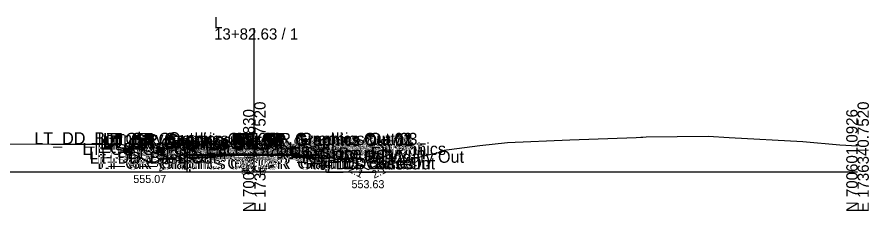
# Model space of a CAD drawing. Extents: x -26 to 697, y -10 to 2642.
# Drawn here: x 91 to 302.8, y 2190.3 to 2238.5 of the extents above; entities that cross this region are included whole.
import ezdxf

# ---------------------------------------------------------------- set-up
doc = ezdxf.new("R2010")
doc.units = 0
for name, color, linetype in [('Default', 7, 'Continuous'), ('Exist CMT Pavement', 7, 'Continuous'), ('Exist Cross Section Cell', 7, 'Continuous'), ('Exist XS Center Line Elevation Label', 7, 'Continuous'), ('Exist XS Ground Line', 7, 'Continuous'), ('Prop CMT Ditch DDE', 7, 'Continuous'), ('Prop CMT Guardrail Graphics', 7, 'Continuous'), ('Prop CMT Pvmt Course 1', 7, 'Continuous'), ('Prop CMT Pvmt Course 1 Wedge', 7, 'Continuous'), ('Prop CMT Pvmt Course 2', 7, 'Continuous'), ('Prop CMT Pvmt Course 2 Wedge', 7, 'Continuous'), ('Prop CMT Pvmt Surface', 7, 'Continuous'), ('Prop CMT Pvmt Surface Shoulder', 7, 'Continuous'), ('Prop CMT Pvmt Wedge Surface 1', 7, 'Continuous'), ('Prop CMT Pvmt Wedge Surface 2', 7, 'Continuous'), ('Prop CMT Shld Paved Course 1', 7, 'Continuous'), ('Prop CMT Shld Paved Course 2', 7, 'Continuous'), ('Prop CMT Slope Grass', 7, 'Continuous'), ('Prop CMT Subgrade Earthwork', 7, 'Continuous'), ('Prop XS Ditch Slope Text', 7, 'Continuous'), ('Prop XS Ditch Standard Text', 7, 'Continuous'), ('Prop XS SE Text', 7, 'Continuous'), ('Prop XS Side Slope Text', 7, 'Continuous')]:
    doc.layers.add(name, color=color, linetype=linetype)

msp = doc.modelspace()

# ---------------------------------------------------------------- linework, layer by layer
at = {"layer": 'Exist CMT Pavement'}
for points in [[(150, 2204.17), (140.37, 2204.02)], [(140.37, 2204.02), (145.19, 2204.1)], [(145.19, 2204.1), (150, 2204.17)], [(154.79, 2204.13), (150, 2204.17)], [(150, 2204.17), (159.58, 2204.09)], [(159.58, 2204.09), (154.79, 2204.13)]]:
    msp.add_lwpolyline(points, dxfattribs=at)
at = {"layer": 'Exist Cross Section Cell'}
for p, q in [((150, 2200), (150, 2235.67)), ((0, 2200), (150, 2200)), ((150, 2200), (300, 2200))]:
    msp.add_line(p, q, dxfattribs=at)
at = {"layer": 'Exist XS Ground Line'}
msp.add_lwpolyline([(89.24, 2206.94), (99.57, 2206.93), (116.83, 2206.87), (124.48, 2204.88), (132.24, 2202.4), (133.49, 2202.76), (135.76, 2203.41), (138.72, 2203.78), (140.37, 2204.02), (148.63, 2204.17), (149.79, 2204.17), (151.03, 2204.16), (159.58, 2204.09), (160.58, 2203.96), (162.84, 2203.7), (166.59, 2202.7), (167.19, 2202.54), (170.32, 2203.17), (171.54, 2203.41), (175.17, 2203.26), (177.21, 2203.12), (179.71, 2202.62), (183.64, 2201.9), (194.2, 2204.49), (195.81, 2204.79), (196.58, 2205.35), (206.07, 2206.6), (212.96, 2207.35), (228.45, 2207.95), (244.94, 2208.55), (246.11, 2208.61), (246.64, 2208.62), (247.45, 2208.68), (262.88, 2208.87), (268.12, 2208.57), (286.38, 2207.55), (295.59, 2206.69), (300, 2206.51)], dxfattribs=at)
at = {"layer": 'Prop CMT Ditch DDE'}
for points in [[(124.59, 2202.07), (114.97, 2206.87)], [(129.73, 2203.2), (126.73, 2203.14), (124.59, 2202.07)], [(170.36, 2203.17), (173.36, 2203.11), (178.34, 2200.63)], [(124.59, 2202.07), (124.59, 2202.07)], [(178.34, 2200.63), (181.62, 2202.27)], [(178.34, 2200.63), (178.34, 2200.63)]]:
    msp.add_lwpolyline(points, dxfattribs=at)
at = {"layer": 'Prop CMT Guardrail Graphics'}
for points in [[(132.68, 2200.71), (132.68, 2206.71)], [(132.68, 2206.71), (134.01, 2206.71), (134.28, 2206.42)], [(134.28, 2205.84), (134.01, 2205.55), (133.34, 2205.55)], [(133.34, 2205.55), (133.34, 2200.71)], [(134.28, 2206.42), (134.01, 2206.13)], [(134.01, 2206.13), (134.28, 2205.84)], [(167.36, 2206.71), (166.03, 2206.71), (165.76, 2206.42)], [(165.76, 2206.42), (166.03, 2206.13)], [(166.03, 2206.13), (165.76, 2205.84)], [(165.76, 2205.84), (166.03, 2205.55), (166.7, 2205.55)], [(166.7, 2205.55), (166.7, 2200.71)], [(167.36, 2200.71), (167.36, 2206.71)], [(133.34, 2200.71), (132.68, 2200.71)], [(166.7, 2200.71), (167.36, 2200.71)]]:
    msp.add_lwpolyline(points, dxfattribs=at)
at = {"layer": 'Prop CMT Pvmt Course 1'}
for points in [[(150, 2204.53), (139, 2204.31)], [(139, 2204.31), (139, 2204.1)], [(139, 2204.1), (140.37, 2204.13)], [(140.37, 2204.23), (150, 2204.42)], [(140.37, 2204.13), (140.37, 2204.23)], [(150, 2204.32), (150, 2204.53)], [(150, 2204.53), (161, 2204.31)], [(150, 2204.32), (150, 2204.53)], [(150, 2204.42), (150, 2204.32), (150, 2204.32)], [(159.58, 2204.23), (150, 2204.42)], [(150, 2204.42), (150, 2204.32), (150, 2204.32)], [(159.58, 2204.13), (159.58, 2204.23)], [(161, 2204.1), (159.58, 2204.13)], [(161, 2204.31), (161, 2204.1)]]:
    msp.add_lwpolyline(points, dxfattribs=at)
at = {"layer": 'Prop CMT Pvmt Course 1 Wedge'}
for points in [[(150, 2204.42), (140.37, 2204.23)], [(150, 2204.42), (159.58, 2204.23)]]:
    msp.add_lwpolyline(points, dxfattribs=at)
at = {"layer": 'Prop CMT Pvmt Course 2'}
for points in [[(140.37, 2204.13), (139, 2204.1)], [(139, 2204.1), (139, 2203.64)], [(139, 2203.64), (140.37, 2203.67)], [(140.37, 2203.67), (140.37, 2204.13)], [(159.58, 2203.67), (159.58, 2204.13)], [(159.58, 2204.13), (161, 2204.1)], [(161, 2203.64), (159.58, 2203.67)], [(161, 2204.1), (161, 2203.64)]]:
    msp.add_lwpolyline(points, dxfattribs=at)
at = {"layer": 'Prop CMT Pvmt Course 2 Wedge'}
for points in [[(150, 2204.32), (140.37, 2204.13)], [(150, 2204.32), (159.58, 2204.13)]]:
    msp.add_lwpolyline(points, dxfattribs=at)
at = {"layer": 'Prop CMT Pvmt Surface'}
for points in [[(150, 2204.53), (139, 2204.31)], [(150, 2204.53), (161, 2204.31)]]:
    msp.add_lwpolyline(points, dxfattribs=at)
at = {"layer": 'Prop CMT Pvmt Surface Shoulder'}
for points in [[(139, 2204.31), (134.29, 2204.21)], [(161, 2204.31), (165.75, 2204.21)]]:
    msp.add_lwpolyline(points, dxfattribs=at)
at = {"layer": 'Prop CMT Pvmt Wedge Surface 1'}
for points in [[(139, 2204.1), (139, 2204.31)], [(140.37, 2204.13), (139, 2204.1)], [(150, 2204.42), (140.37, 2204.23)], [(140.37, 2204.23), (140.37, 2204.13)], [(150, 2204.53), (150, 2204.32), (150, 2204.32), (150, 2204.42)], [(150, 2204.53), (150, 2204.32), (150, 2204.32), (150, 2204.42)], [(150, 2204.42), (159.58, 2204.23)], [(159.58, 2204.23), (159.58, 2204.13)], [(159.58, 2204.13), (161, 2204.1)], [(161, 2204.1), (161, 2204.31)]]:
    msp.add_lwpolyline(points, dxfattribs=at)
at = {"layer": 'Prop CMT Pvmt Wedge Surface 2'}
for points in [[(150, 2204.32), (139, 2204.1)], [(139, 2204.1), (139, 2204.31)], [(150, 2204.53), (150, 2204.32)], [(150, 2204.53), (150, 2204.32)], [(150, 2204.32), (161, 2204.1)], [(161, 2204.1), (161, 2204.31)]]:
    msp.add_lwpolyline(points, dxfattribs=at)
at = {"layer": 'Prop CMT Shld Paved Course 1'}
for points in [[(139, 2204.31), (134.29, 2204.21), (134.08, 2204)], [(134.08, 2204), (139, 2204.1)], [(139, 2204.1), (139, 2204.31)], [(161, 2204.31), (165.75, 2204.21), (165.96, 2204)], [(161, 2204.1), (161, 2204.31)], [(165.96, 2204), (161, 2204.1)]]:
    msp.add_lwpolyline(points, dxfattribs=at)
at = {"layer": 'Prop CMT Shld Paved Course 2'}
for points in [[(139, 2204.1), (134.08, 2204), (134.07, 2204), (133.6, 2203.53)], [(133.6, 2203.53), (139, 2203.64)], [(139, 2203.64), (139, 2204.1)], [(161, 2204.1), (165.96, 2204), (165.97, 2204), (166.44, 2203.53)], [(161, 2203.64), (161, 2204.1)], [(166.44, 2203.53), (161, 2203.64)]]:
    msp.add_lwpolyline(points, dxfattribs=at)
at = {"layer": 'Prop CMT Slope Grass'}
for points in [[(131.28, 2203.97), (129.73, 2203.2)], [(134.28, 2204.21), (131.28, 2203.97)], [(134.29, 2204.21), (134.28, 2204.21)], [(165.75, 2204.21), (165.76, 2204.21)], [(165.76, 2204.21), (168.76, 2203.97)], [(168.76, 2203.97), (170.36, 2203.17)]]:
    msp.add_lwpolyline(points, dxfattribs=at)
at = {"layer": 'Prop CMT Subgrade Earthwork'}
for points in [[(133.6, 2203.53), (133.02, 2204.11)], [(139, 2203.64), (133.6, 2203.53)], [(140.37, 2203.67), (139, 2203.64)], [(140.37, 2203.67), (140.39, 2204.02)], [(159.58, 2203.67), (159.56, 2204.09)], [(159.58, 2203.67), (161, 2203.64)], [(161, 2203.64), (166.44, 2203.53)], [(166.44, 2203.53), (167.02, 2204.11)]]:
    msp.add_lwpolyline(points, dxfattribs=at)

# ---------------------------------------------------------------- texts
at = {"layer": 'Default'}
for s, p in [('LT_DD_Boundary Out', (95.31, 2206.87)), ('LT_GR_Graphics Out 03', (111.03, 2206.71)), ('LT_GR_Graphics Out 02', (112.41, 2206.71)), ('LT_GR_Graphics Out 01', (113.12, 2206.42)), ('RT_GR_Graphics Out 02', (144.26, 2206.71)), ('RT_GR_Graphics Out 01', (144.42, 2206.42)), ('RT_GR_Graphics Out 03', (145.54, 2206.71)), ('LT_GS_OS_GR_Face_Graphics', (107.27, 2204.21)), ('LT_GR_Graphics Out 06', (111.66, 2205.55)), ('LT_GR_Graphics Out 07', (112.28, 2205.55)), ('LT_GR_Graphics Out 09', (112.33, 2206.13)), ('LT_GR_Graphics Out 08', (112.59, 2205.84)), ('LT_PV1_OEOT', (126.6, 2204.31)), ('RT_PV2_IEEOP', (137.14, 2204.32)), ('LT_PV2_IEEOP', (137.32, 2204.32)), ('RT_PV1_IEEOP', (137.5, 2204.42)), ('LT_PV1_IEEOP', (137.68, 2204.42)), ('RT_GS_OS_GR_Face_Graphics', (138.57, 2204.21)), ('PV2_PGL', (142.05, 2204.32)), ('PV1_PGL', (142.41, 2204.53)), ('RT_GR_Graphics Out 08', (143.9, 2205.84)), ('RT_GR_Graphics Out 07', (144.13, 2205.55)), ('RT_GR_Graphics Out 09', (144.18, 2206.13)), ('RT_GR_Graphics Out 06', (144.84, 2205.55)), ('RT_PV1_OEOT', (148.42, 2204.31)), ('LT_DD_Boundary In', (108.91, 2203.14)), ('LT_Sub_Trench_Out_DLT', (110.97, 2204.11)), ('LT_Sub_Trench_Out', (115.93, 2203.53)), ('LT_GS_OS_CTL', (117.67, 2203.97)), ('LT_PS2_Shelf_Out', (118.04, 2204)), ('LT_Slope_Fill', (118.44, 2203.2)), ('LT_PS2_OEOP', (121.44, 2204)), ('LT_PS1_OEOP', (122.01, 2204.21)), ('LT_PV_Sub_Tie_Out', (122.88, 2204.02)), ('LT_PV_OEEOP_EG', (124.16, 2204.02)), ('LT_PV2_OEOT', (126.24, 2204.1)), ('LT_Sub_OEOT', (126.31, 2203.64)), ('LT_PV2_OEEOP', (126.55, 2204.13)), ('LT_Sub_OEEOP', (126.62, 2203.67)), ('LT_PV1_OEEOP', (126.91, 2204.23)), ('LT_PV_EG_TestPt', (130.31, 2204.1)), ('RT_PV_IEEOP_EG', (134.76, 2204.17)), ('LT_PV_IEEOP_EG', (134.93, 2204.17)), ('RT_PV_EG_TestPt', (139.73, 2204.13)), ('RT_PV_Sub_Tie_Out', (141.88, 2204.09)), ('RT_PV_OEEOP_EG', (143.19, 2204.09)), ('RT_Sub_Trench_Out_DLT', (144.79, 2204.11)), ('RT_PV2_OEEOP', (145.58, 2204.13)), ('RT_Sub_OEEOP', (145.65, 2203.67)), ('RT_PV1_OEEOP', (145.94, 2204.23)), ('RT_PV2_OEOT', (148.06, 2204.1)), ('RT_Sub_OEOT', (148.13, 2203.64)), ('RT_Sub_Trench_Out', (148.59, 2203.53)), ('RT_PS2_Shelf_Out', (149.77, 2204)), ('RT_PS2_OEOP', (153.14, 2204)), ('RT_PS1_OEOP', (153.29, 2204.21)), ('RT_GS_OS_CTL', (154.97, 2203.97)), ('RT_DD_Boundary In', (155.36, 2203.11)), ('RT_Slope_Fill', (158.9, 2203.17)), ('RT_DD_Boundary Out', (161.79, 2202.27)), ('LT_DD_Base Out', (109.09, 2202.07)), ('LT_DD_Base In', (110.92, 2202.07)), ('LT_GR_Graphics Out 04', (110.98, 2200.71)), ('LT_GR_Graphics Out 05', (111.68, 2200.71)), ('RT_GR_Graphics Out 05', (144.86, 2200.71)), ('RT_GR_Graphics Out 04', (145.49, 2200.71)), ('RT_DD_Base Out', (162.66, 2200.63)), ('RT_DD_Base In', (164.49, 2200.63))]:
    msp.add_text(s, height=3, dxfattribs=at).set_placement(p)
at = {"layer": 'Exist Cross Section Cell'}
for s, p in [('L', (140, 2235.67)), ('13+82.63 / 1', (140, 2232.87))]:
    msp.add_text(s, height=2.8, dxfattribs=at).set_placement(p)
for s, p in [('E 1736194.7520', (152.8, 2190)), ('E 1736340.7520', (302.8, 2190)), ('N 700566.6830', (150, 2190)), ('N 700601.0926', (300, 2190))]:
    msp.add_text(s, height=2.8, rotation=90, dxfattribs=at).set_placement(p)
at = {"layer": 'Exist XS Center Line Elevation Label'}
msp.add_text('557.17', height=1.6, dxfattribs=at).set_placement((146.75, 2199.37))
at = {"layer": 'Prop XS Ditch Slope Text'}
for rotation, p in [(333.4349, (117.13, 2202.72)), (26.5651, (126.38, 2200)), (333.4349, (173.2, 2200.12)), (26.5651, (179.79, 2198.28))]:
    msp.add_text('2:1', height=2, rotation=rotation, dxfattribs=at).set_placement(p)
at = {"layer": 'Prop XS Ditch Standard Text'}
for s, p in [('555.07', (119.92, 2197.25)), ('553.63', (174.17, 2195.95))]:
    msp.add_text(s, height=2, dxfattribs=at).set_placement(p)
at = {"layer": 'Prop XS SE Text'}
for rotation, p in [(1.1458, (140.98, 2205.35)), (358.8542, (152.02, 2205.49))]:
    msp.add_text('0.020', height=2, rotation=rotation, dxfattribs=at).set_placement(p)
at = {"layer": 'Prop XS Side Slope Text'}
for rotation, p in [(26.565, (128.75, 2203.55)), (333.4422, (168.48, 2204.95))]:
    msp.add_text('2:1', height=2, rotation=rotation, dxfattribs=at).set_placement(p)

doc.saveas('drawing.dxf')
